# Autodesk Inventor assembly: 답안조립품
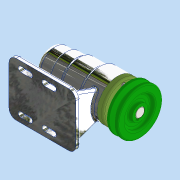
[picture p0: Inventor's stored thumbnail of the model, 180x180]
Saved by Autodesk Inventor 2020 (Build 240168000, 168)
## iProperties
Created: 2021-10
Part Number: 답안조립품
Document SubType Name: Assembly
Designer: user
Author: user
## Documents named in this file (12)
- C:\Users\user\Desktop\711007V1010\답안조립품.iam
- C:\Users\user\Desktop\711007V1010\V벨트풀리.ipt
- C:\Users\user\Desktop\711007V1010\멈춤나사 M3.ipt
- C:\Users\user\Desktop\711007V1010\베어링 6004.ipt
- C:\Users\user\Desktop\711007V1010\베어링 51202.ipt
- C:\Users\user\Desktop\711007V1010\본체.ipt
- C:\Users\user\Desktop\711007V1010\볼트 M4.ipt
- C:\Users\user\Desktop\711007V1010\어댑터슬리브.ipt
- C:\Users\user\Desktop\711007V1010\오일 실 20x35x7.ipt
- C:\Users\user\Desktop\711007V1010\축.ipt
- C:\Users\user\Desktop\711007V1010\커버.ipt
- C:\Users\user\Desktop\711007V1010\키 5x5.ipt
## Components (1 placed, 1 different names)
1. V벨트풀리:1
